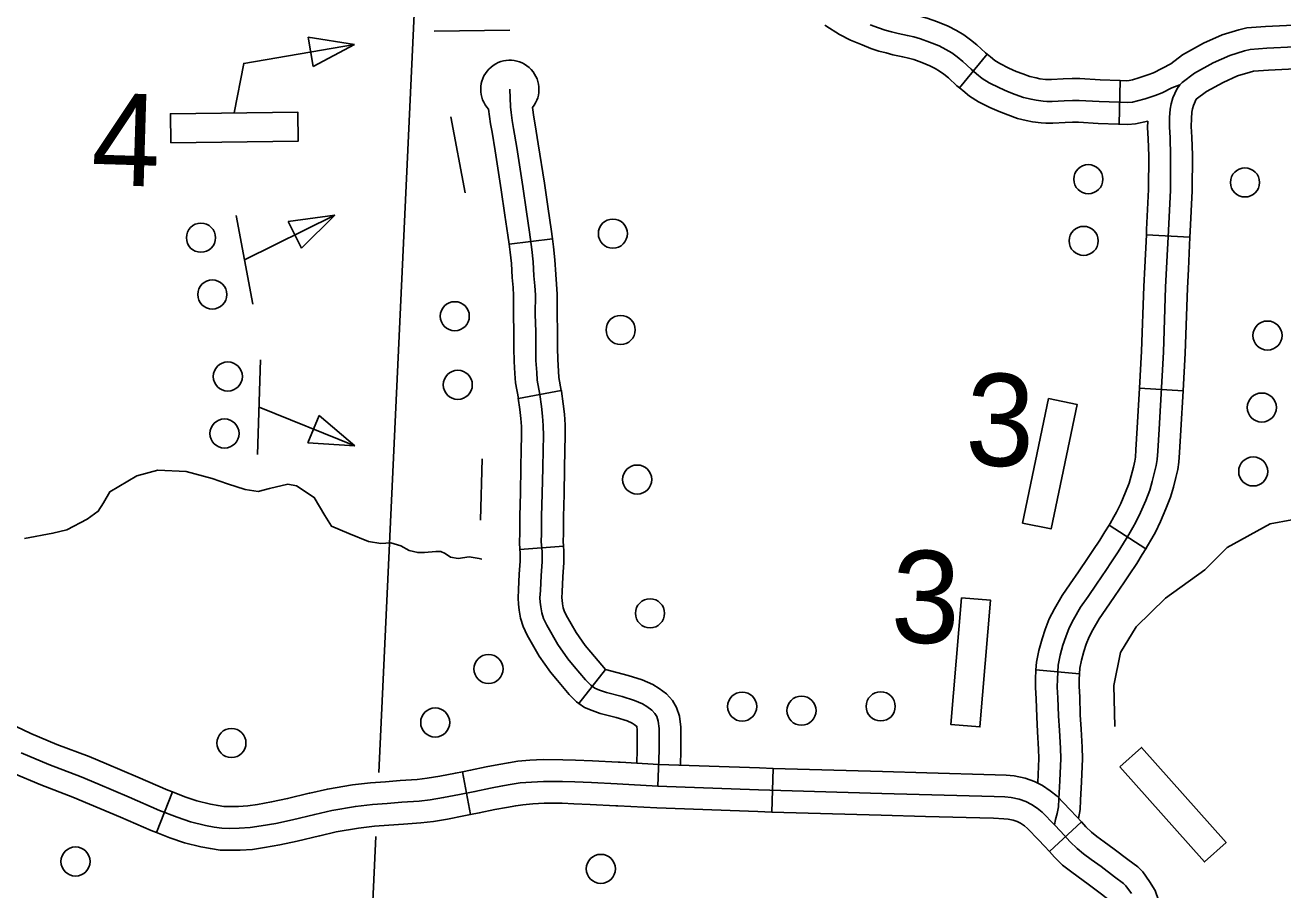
# Model space of a CAD drawing. Extents: x 653372 to 905732, y 627442 to 787275.
# Drawn here: x 709737 to 714058, y 758143 to 761114 of the extents above; entities that cross this region are included whole.
import ezdxf

# ---------------------------------------------------------------- set-up
doc = ezdxf.new("R2010")
doc.units = 0
for name, color, linetype in [('31', 7, 'Continuous'), ('32', 7, 'Continuous'), ('35', 7, 'Continuous'), ('5', 7, 'Continuous'), ('56', 7, 'Continuous')]:
    doc.layers.add(name, color=color, linetype=linetype)

msp = doc.modelspace()

# ---------------------------------------------------------------- linework, layer by layer
at = {"layer": '31'}
for p, q in [((711266.8, 758401), (711239.4, 758548.5)), ((711239.4, 758548.5), (711239.4, 758548.5)), ((712307.2, 758560), (712302.7, 758410)), ((710243, 758479), (710188.8, 758339.2)), ((713255.9, 758274.1), (713366.1, 758375.9))]:
    msp.add_line(p, q, dxfattribs=at)
for points in [[(709238.7, 758833), (709264.6, 758827.5), (709357.5, 758806.8), (709445.2, 758785.6), (709488.3, 758774.9), (709560.8, 758756.9), (709619.7, 758738.5), (709668.7, 758718.9), (709708.8, 758703.1), (709754.5, 758681.5), (709757.4, 758680.3)], [(709757.4, 758680.3), (709846.6, 758642.6), (709957.7, 758600.6), (710016.4, 758575.5), (710124.4, 758530.3), (710227.3, 758485.1), (710243, 758479)], [(710198.6, 758415.8), (710094.8, 758461.4), (709987.2, 758506.4), (709929.6, 758531), (709818.8, 758573), (709723.9, 758613.1)], [(711239.4, 758548.5), (711267.8, 758553.7), (711321.5, 758565.4), (711364.1, 758573.3), (711397.8, 758579.5), (711429.4, 758584.3), (711471.6, 758587.9), (711516.7, 758590), (711584.8, 758589.9), (711628.1, 758588.6), (711685.9, 758586.2), (711775, 758581.6), (711781.7, 758581.3)], [(711781.7, 758581.3), (711914.2, 758573.7), (712259.6, 758561.4), (712307.2, 758560)], [(710188.8, 758339.2), (710170, 758346.4), (710065.3, 758392.4), (709958, 758437.3), (709901.6, 758461.4), (709790.9, 758503.3), (709699, 758542.1)], [(711239.4, 758548.5), (711215.6, 758544), (711161.5, 758533.1), (711118.7, 758526.1), (711083.5, 758522), (711025.7, 758518.2), (710975.7, 758514), (710924, 758510.3), (710861.7, 758503.4), (710776, 758488.7), (710714.8, 758474.7), (710713.3, 758474.3)], [(712834.7, 758544.6), (712682.3, 758548.7), (712307.2, 758560)], [(713366.1, 758375.9), (713348.6, 758394.8), (713327.5, 758417.5), (713282.3, 758464.5), (713258.6, 758483.4), (713232.7, 758500.7), (713205, 758515.2), (713172.6, 758526.5), (713134.6, 758534.9), (713107.4, 758536.6), (713069.4, 758538.3), (712834.7, 758544.6)], [(713537.5, 758129.9), (713518.9, 758156), (713510.7, 758164.3), (713479.7, 758187.4), (713433.9, 758222.3), (713399.1, 758247.4), (713373.7, 758266.6), (713350.8, 758284.4), (713327.4, 758307.3), (713293.7, 758343.8), (713273, 758365.9), (713231.6, 758409), (713214.3, 758422.8), (713194.4, 758436.1), (713175.1, 758446.2), (713152, 758454.3), (713124.2, 758460.4), (713103.3, 758461.7), (713066.6, 758463.4), (712680.2, 758473.7), (712257.2, 758486.4), (711910.7, 758498.8), (711771, 758506.7), (711682.4, 758511.3), (711625.4, 758513.6), (711583.7, 758514.9), (711518.4, 758515), (711476.5, 758513), (711438.2, 758509.8), (711410.2, 758505.5), (711377.7, 758499.5), (711336.3, 758491.9), (711282.7, 758480.2), (711229.8, 758470.4), (711175, 758459.4), (711129.1, 758451.9), (711090.4, 758447.3), (711031.3, 758443.4), (710981.5, 758439.2), (710930.7, 758435.6), (710872.2, 758429.1), (710790.7, 758415.1), (710732, 758401.7), (710655.4, 758383.1), (710598, 758370.8), (710547.7, 758362.2), (710510.5, 758356.3), (710473, 758354.3), (710438.8, 758353.4), (710413.5, 758354.2), (710387, 758358.2), (710357.4, 758364.1), (710305.9, 758376.7), (710260.1, 758392), (710198.6, 758415.8)], [(710713.3, 758474.3), (710638.8, 758456.2), (710583.9, 758444.5), (710535.6, 758436.2), (710502.6, 758431), (710470, 758429.3), (710439, 758428.5), (710420.2, 758429), (710399.9, 758432), (710373.7, 758437.3), (710326.7, 758448.8), (710285.5, 758462.5), (710243, 758479)], [(711773.2, 758431.5), (711766.9, 758431.8), (711678.9, 758436.4), (711622.8, 758438.7), (711582.5, 758439.9), (711520.1, 758440), (711481.4, 758438.2), (711447, 758435.2), (711422.6, 758431.6), (711391.3, 758425.8), (711351.1, 758418.4), (711297.5, 758406.7), (711266.8, 758401)], [(711266.8, 758401), (711244, 758396.7), (711188.4, 758385.6), (711139.6, 758377.6), (711097.2, 758372.6), (711037, 758368.6), (710987.3, 758364.4), (710937.5, 758360.9), (710882.7, 758354.9), (710805.5, 758341.6), (710749.2, 758328.7), (710748.8, 758328.6)], [(712302.7, 758410), (712254.7, 758411.5), (711907.3, 758423.9), (711773.2, 758431.5)], [(712830.7, 758394.7), (712678.1, 758398.8), (712302.7, 758410)], [(713255.9, 758274.1), (713238.7, 758292.7), (713218.6, 758314.4), (713181, 758353.5), (713170, 758362.2), (713156.2, 758371.5), (713145.2, 758377.2), (713131.5, 758382), (713113.8, 758385.9), (713099.3, 758386.8), (713063.9, 758388.4), (712830.7, 758394.7)], [(713366.1, 758375.9), (713381.2, 758359.5), (713400.2, 758341), (713419.3, 758326.1), (713443.7, 758307.8), (713478.6, 758282.6), (713524.9, 758247.2), (713559.9, 758221.1), (713576.4, 758204.6), (713599.9, 758171.5), (713619.1, 758140.8), (713630.6, 758106.8), (713636.4, 758082.3), (713639.8, 758051.1), (713640.2, 758014.5), (713637.7, 757953.4), (713634.9, 757904.1)], [(710748.8, 758328.6), (710672.1, 758309.9), (710612.2, 758297.2), (710559.9, 758288.2), (710518.4, 758281.7), (710476, 758279.4), (710438.6, 758278.4), (710406.8, 758279.4), (710374, 758284.3), (710341.1, 758290.9), (710285.1, 758304.5), (710234.6, 758321.4), (710188.8, 758339.2)], [(713485.1, 757912.4), (713487.8, 757960.6), (713490.1, 758016.7), (713489.8, 758042.2), (713488.3, 758056.8), (713486.2, 758065.4), (713482.6, 758076.3), (713475.1, 758088.2), (713461.4, 758107.4), (713434.5, 758127.5), (713389.1, 758162.1), (713354.6, 758187.1), (713328.1, 758207), (713301.4, 758227.8), (713273.6, 758255), (713255.9, 758274.1)]]:
    msp.add_lwpolyline(points, dxfattribs=at)
at = {"layer": '32'}
for p, q in [((712947.1, 760898.2), (713042.3, 761014.2)), ((713495.1, 760773.8), (713499.6, 760923.7)), ((711399.9, 760361.3), (711548.7, 760380.2)), ((713738.9, 760385.5), (713589.1, 760393)), ((713715.3, 759857.7), (713565.5, 759866)), ((711431.9, 759830.5), (711579.2, 759858.7)), ((713587.1, 759314.6), (713460.9, 759395.6)), ((711437.2, 759311.6), (711586.7, 759323.3)), ((711638.9, 758782.9), (711730.9, 758899.6)), ((713359.2, 758885.3), (713209.8, 758898.4))]:
    msp.add_line(p, q, dxfattribs=at)
for points in [[(712562.1, 761242.2), (712567.6, 761238.9), (712609.2, 761212.3), (712635.9, 761198.6), (712668.7, 761185.2), (712694.5, 761174.8), (712713.2, 761168.6), (712731.8, 761163.8), (712753.8, 761158.4), (712784.4, 761151.2), (712807.9, 761146.4), (712836.3, 761138.2), (712871.2, 761125.6), (712908, 761110.8), (712936.8, 761096), (712962.6, 761080.7), (712984.9, 761063.9), (713007.1, 761046.2), (713036.6, 761018.8), (713042.3, 761014.2)], [(712484.2, 761114), (712488.2, 761111.6), (712534.4, 761082), (712573.2, 761062.1), (712612.6, 761046.1), (712642.8, 761034), (712670.6, 761024.6), (712695.2, 761018.3), (712718.7, 761012.5), (712752.1, 761004.7), (712771.9, 761000.6), (712790, 760995.4), (712817.8, 760985.4), (712845.6, 760974.2), (712864.1, 760964.7), (712879, 760955.8), (712893, 760945.3), (712909.2, 760932.4), (712938, 760905.7), (712947.1, 760898.2)], [(712640.6, 761115.6), (712668.7, 761104.4), (712691.9, 761096.6), (712713.5, 761091.1), (712736.3, 761085.5), (712768.2, 761078), (712789.9, 761073.5), (712813.2, 761066.8), (712844.5, 761055.5), (712876.8, 761042.5), (712900.4, 761030.3), (712920.8, 761018.3), (712938.9, 761004.6), (712958.1, 760989.3), (712987.3, 760962.3), (713005.9, 760947), (713025.1, 760931.1), (713049.2, 760916.2), (713084.1, 760898.8), (713112.3, 760885.9), (713138.7, 760875.9), (713167.3, 760865.7), (713193.3, 760859.5), (713210.7, 760855.7), (713235.1, 760852.8), (713247.1, 760851.9), (713265.7, 760851.9), (713307, 760854.4), (713334.9, 760855.2), (713357.8, 760855.1), (713426.9, 760851.4), (713495.6, 760848.8), (713523.4, 760847.9), (713540.9, 760849.6), (713559, 760853.4), (713584.9, 760860.8), (713619.6, 760872.3), (713643.8, 760881.4), (713676.5, 760898.5), (713703.6, 760909.4)], [(714160, 761116.2), (714148.1, 761115.3), (714094.6, 761113.8), (713998.6, 761109.3), (713934.3, 761104.2), (713906.3, 761097.7), (713849.9, 761080.4), (713785.7, 761051.8), (713713.3, 761011.9), (713672.7, 760981)], [(714097.5, 761038.9), (714003.3, 761034.4), (713945.8, 761029.9), (713925.8, 761025.2), (713876.2, 761010), (713819.1, 760984.6), (713754.3, 760948.9), (713712.4, 760917), (713703.6, 760909.4)], [(713042.3, 761014.2), (713053.6, 761004.8), (713068.9, 760992.2), (713085.7, 760981.8), (713116.4, 760966.5), (713141.3, 760955.2), (713164.6, 760946.3), (713188.7, 760937.7), (713210.1, 760932.6), (713223.2, 760929.7), (713242.4, 760927.4), (713250, 760926.9), (713263.3, 760926.9), (713303.6, 760929.4), (713334, 760930.2), (713360, 760930.1), (713430.4, 760926.3), (713498.1, 760923.7), (713499.6, 760923.7)], [(713499.6, 760923.7), (713521, 760923), (713529.6, 760923.9), (713540.9, 760926.3), (713562.7, 760932.5), (713594.6, 760943.1), (713613.2, 760950.1), (713672.7, 760981)], [(714170.7, 760966.5), (714155.5, 760965.5), (714100.3, 760963.9), (714008.1, 760959.5), (713957.2, 760955.5), (713945.3, 760952.8), (713902.6, 760939.6), (713852.5, 760917.3), (713795.3, 760885.9), (713760.5, 760859.3)], [(712947.1, 760898.2), (712958.2, 760889.1), (712981.2, 760870), (713012.6, 760850.6), (713051.8, 760831.1), (713083.4, 760816.7), (713112.9, 760805.5), (713146, 760793.7), (713176.6, 760786.4), (713198.2, 760781.7), (713227.9, 760778.1), (713244.3, 760776.9), (713268, 760776.9), (713310.4, 760779.5), (713335.7, 760780.2), (713355.5, 760780.1), (713423.5, 760776.5), (713493, 760773.8), (713495.1, 760773.8)], [(713273, 758365.9), (713277.3, 758384.1), (713282.4, 758404.6), (713286.9, 758428.1), (713288.5, 758455), (713291.8, 758517.1), (713294.9, 758593.5), (713293.7, 758629), (713290.3, 758690.2), (713287.3, 758740.2), (713285, 758802.6), (713283.1, 758839.3), (713283.3, 758866.3), (713284.4, 758891), (713286.5, 758915), (713292.8, 758948.5), (713302.5, 758983.6), (713311.9, 759011.8), (713324.1, 759043.3), (713339.2, 759072), (713363, 759114.4), (713388.8, 759150.8), (713418.2, 759193), (713451.8, 759243.3), (713467.5, 759266.6), (713492.6, 759303.7), (713510.4, 759333.9), (713529.2, 759363.3), (713542.7, 759387.3), (713553.4, 759406.1), (713569.1, 759439.5), (713587.2, 759480.6), (713601, 759516.1), (713609.4, 759545.5), (713617.5, 759577.5), (713623.1, 759601.1), (713626.3, 759621.3), (713628.3, 759649.7), (713632.8, 759726), (713647.5, 759989.9), (713655.3, 760213.1), (713658.4, 760279), (713664.9, 760408.2), (713671.7, 760546.7), (713672.3, 760665.7), (713670.4, 760726.5), (713668.5, 760764.4), (713668.7, 760796.2), (713671.3, 760824.8), (713674.4, 760843.1), (713680.5, 760863.7), (713693.9, 760894.1), (713703.6, 760909.4)], [(711402.4, 760893.5), (711404.3, 760833.1), (711406.7, 760813.9), (711410.3, 760786.5), (711415.3, 760758.4), (711425.9, 760693.9), (711446.9, 760559.2), (711459.8, 760471.9), (711470.2, 760403), (711477.8, 760342.9), (711482.5, 760300.8), (711485.4, 760252.1), (711488.1, 760218.1), (711490.1, 760187.1), (711489.6, 760120.8), (711491.4, 760059.6), (711491.2, 760004.3), (711492.2, 759961.5), (711494.6, 759920.9), (711496, 759894.3), (711505.6, 759844.5), (711511, 759803.1), (711515.1, 759769.8), (711517.1, 759738.1), (711517.5, 759702.7), (711516.8, 759654.8), (711515.7, 759592.2), (711513.8, 759504.6), (711511.4, 759425.8), (711511.2, 759367.6), (711510.3, 759338.7), (711513, 759304.7), (711513.4, 759269.4), (711509.8, 759223), (711507.5, 759170.8), (711506, 759145.8), (711507, 759131), (711508.7, 759114.7), (711512.5, 759094), (711518.6, 759074.6), (711529, 759052.2), (711566.8, 758986.2), (711601.4, 758936.6), (711623.3, 758910.5), (711662.4, 758864.4), (711680.3, 758845.5), (711694.7, 758835.4), (711710.7, 758829.1), (711734.8, 758821), (711788.1, 758806.8), (711831.2, 758793.8), (711858.1, 758781.9), (711872.5, 758772.6), (711889.8, 758759.6), (711900.5, 758748.2), (711906.9, 758737.7), (711912.3, 758722.1), (711915.2, 758696.9), (711915.2, 758622.5), (711910.7, 758498.8)], [(713738.9, 760385.5), (713739.8, 760404.5), (713746.7, 760544.6), (713747.3, 760666.7), (713745.3, 760729.5), (713743.5, 760766), (713743.7, 760792.7), (713745.7, 760815.1), (713747.6, 760826), (713751.1, 760837.9), (713760.5, 760859.3)], [(711329.6, 760825), (711336.1, 760775), (711341.4, 760745.7), (711351.9, 760682.1), (711372.8, 760548), (711385.6, 760460.8), (711395.9, 760392.6), (711399.9, 760361.3)], [(711480.1, 760830.5), (711484.4, 760798), (711489.2, 760771.1), (711500, 760705.8), (711521.1, 760570.4), (711533.9, 760482.9), (711544.5, 760413.4), (711548.7, 760380.2)], [(713495.1, 760773.8), (713525.8, 760772.8), (713552.2, 760775.3), (713593.6, 760784.1)], [(713589.1, 760393), (713590, 760411.9), (713596.7, 760548.7), (713597.3, 760664.7), (713595.4, 760723.5), (713593.5, 760762.8), (713593.6, 760784.1)], [(711548.7, 760380.2), (711552.3, 760351.8), (711557.2, 760307.2), (711560.2, 760257.3), (711562.9, 760223.5), (711565.1, 760189.2), (711564.6, 760121.6), (711566.4, 760060.6), (711566.2, 760005), (711567.1, 759964.6), (711569.5, 759925.2), (711570.7, 759903.4), (711579.2, 759858.7)], [(713565.5, 759866), (713572.6, 759993.3), (713580.4, 760216.2), (713583.5, 760282.7), (713589.1, 760393)], [(713715.3, 759857.7), (713722.4, 759986.5), (713730.3, 760210.1), (713733.3, 760275.4), (713738.9, 760385.5)], [(711399.9, 760361.3), (711403.4, 760334.1), (711407.7, 760294.4), (711410.6, 760246.9), (711413.3, 760212.7), (711415.1, 760184.9), (711414.6, 760119.9), (711416.4, 760058.5), (711416.2, 760003.6), (711417.2, 759958.4), (711419.8, 759916.7), (711421.4, 759885.2), (711431.9, 759830.5)], [(711579.1, 759859.2), (711579.6, 759856.7), (711585.4, 759812.6), (711589.9, 759776.8), (711592.1, 759740.9), (711592.6, 759702.6), (711591.8, 759653.6), (711590.7, 759590.7), (711588.8, 759502.6), (711586.4, 759424.5), (711586.2, 759366.3), (711585.4, 759340.5), (711586.7, 759323.3)], [(713460.9, 759395.6), (713464.9, 759401.9), (713477.4, 759424.1), (713486.8, 759440.6), (713500.9, 759470.6), (713517.9, 759509.3), (713529.9, 759540), (713537, 759565), (713544.6, 759595.3), (713549.5, 759615.7), (713551.7, 759629.8), (713553.4, 759654.5), (713557.9, 759730.3), (713565.5, 759866)], [(711431.6, 759832.4), (711436.6, 759793.6), (711440.4, 759762.8), (711442.2, 759735.3), (711442.5, 759702.8), (711441.9, 759656), (711440.7, 759593.7), (711438.8, 759506.5), (711436.4, 759427.1), (711436.2, 759368.9), (711435.2, 759336.9), (711437.2, 759311.5)], [(713587.1, 759314.6), (713593.5, 759324.7), (713608, 759350.4), (713620, 759371.5), (713637.4, 759408.4), (713656.5, 759451.9), (713672.2, 759492.2), (713681.9, 759526), (713690.4, 759559.7), (713696.7, 759586.5), (713700.9, 759612.7), (713703.1, 759644.9), (713707.7, 759721.7), (713715.3, 759857.7)], [(713209.8, 758898.4), (713212.1, 758925.1), (713219.6, 758965.4), (713230.7, 759005.5), (713241.4, 759037.2), (713255.7, 759074.3), (713273.3, 759107.8), (713299.5, 759154.6), (713327.4, 759193.9), (713356.2, 759235.3), (713389.5, 759285.1), (713405.3, 759308.5), (713429.1, 759343.7), (713446.5, 759373.2), (713460.9, 759395.6)], [(711437.2, 759311.6), (711438, 759301.4), (711438.3, 759271.8), (711434.9, 759227.6), (711432.6, 759174.7), (711430.8, 759145.4), (711432.3, 759124.4), (711434.4, 759104), (711439.6, 759076), (711448.5, 759047.6), (711462.3, 759017.8), (711503.3, 758946.1), (711541.8, 758890.9), (711566, 758862.1), (711606.5, 758814.4), (711631, 758788.3), (711638.9, 758782.8)], [(711586.7, 759323.3), (711587.9, 759308.1), (711588.4, 759266.9), (711584.6, 759218.5), (711582.4, 759166.9), (711581.1, 759146.2), (711581.7, 759137.6), (711583, 759125.5), (711585.5, 759112), (711588.7, 759101.7), (711595.7, 759086.7), (711630.2, 759026.4), (711660.9, 758982.3), (711680.6, 758959), (711730.9, 758899.6)], [(713359.2, 758885.3), (713360.9, 758904.8), (713365.9, 758931.6), (713374.2, 758961.6), (713382.5, 758986.3), (713392.5, 759012.2), (713405.1, 759036.3), (713426.4, 759074.3), (713450.1, 759107.6), (713480.1, 759150.7), (713514.1, 759201.5), (713529.7, 759224.6), (713556, 759263.6), (713574.3, 759294.6), (713587.1, 759314.6)], [(711730.9, 758899.6), (711808.6, 758879), (711857.3, 758864.2), (711893.7, 758848.2), (711915.5, 758834.2), (711940.1, 758815.6), (711960.7, 758793.7), (711975.2, 758769.6), (711985.8, 758738.9), (711990.2, 758701.3), (711990.2, 758621.1), (711988.4, 758571.1)], [(713216.5, 758511.6), (713219.8, 758593.8), (713218.7, 758625.7), (713215.4, 758685.9), (713212.4, 758736.6), (713210.1, 758799.3), (713208.1, 758837.7), (713208.3, 758868.3), (713209.6, 758896), (713209.8, 758898.4)], [(713355.5, 758387.4), (713361.5, 758418.9), (713363.3, 758450.9), (713366.7, 758513.6), (713369.9, 758593.2), (713368.6, 758632.4), (713365.1, 758694.5), (713362.2, 758743.8), (713360, 758805.8), (713358.1, 758841), (713358.3, 758864.4), (713359.3, 758886.1), (713359.2, 758885.3)], [(711638.9, 758782.9), (711659, 758768.9), (711684.9, 758758.6), (711713.2, 758749.1), (711767.6, 758734.7), (711805.1, 758723.3), (711822.5, 758715.6), (711829.6, 758711), (711838.9, 758704.1), (711840.2, 758692.6), (711840.2, 758623.8), (711838.5, 758578)]]:
    msp.add_lwpolyline(points, dxfattribs=at)
msp.add_arc((711402.4, 760893.5), 100, 320.9907, 223.2344, dxfattribs=at)
at = {"layer": '35'}
for points in [[(711305.9, 759278.6), (711296.9, 759281), (711262.8, 759286.7), (711225.3, 759281.6), (711199, 759285.5), (711180.7, 759298.5), (711165.3, 759305.2), (711148.2, 759305.7), (711109.2, 759302.2), (711085.8, 759301.4), (711056.4, 759308.5), (711027.4, 759324.9), (710993.4, 759335.3), (710959.1, 759333.2), (710917.3, 759339.1), (710849.6, 759367.6), (710789.7, 759392.8), (710767.4, 759429.3), (710730.4, 759491.1), (710669.3, 759530.6), (710639.9, 759536.2), (710577.2, 759522.2), (710537.9, 759510.9), (710493, 759518.5), (710432.9, 759537.4), (710379.6, 759556.2), (710290.6, 759579.8), (710193.7, 759585.1), (710121.5, 759565.5), (710028, 759510.7), (710006.6, 759472.4), (709988.6, 759443.3), (709950.5, 759416.4), (709880.9, 759379.6), (709833, 759367.8), (709735.2, 759349.7)], [(714882.6, 759071.4), (714741.9, 759131.5), (714645.6, 759185.6), (714523.2, 759279.3), (714423.9, 759360.6), (714331.5, 759410.3), (714245.9, 759428.6), (714179.3, 759426.7), (714089, 759413.7), (714014.2, 759400.3), (713867, 759318.6), (713790.3, 759242.6), (713654.4, 759144.9), (713553.6, 759046.2), (713500, 758957.8), (713477.1, 758844.9), (713480.7, 758703.9)]]:
    msp.add_lwpolyline(points, dxfattribs=at)
at = {"layer": '5'}
for points in [[(711075.2, 761176.6), (710952.7, 758545.9)], [(710942.4, 758325.4), (710892.9, 757262.5)]]:
    msp.add_lwpolyline(points, dxfattribs=at)
at = {"layer": '56'}
for p, q in [((710709.2, 761072.2), (710868.7, 761048)), ((710726.6, 760971.7), (710709.2, 761072.2)), ((710868.7, 761048), (710726.6, 760971.7)), ((710640.9, 760439), (710800.7, 760461.3)), ((710686.2, 760347.6), (710640.9, 760439)), ((710800.7, 760461.3), (710686.2, 760347.6)), ((710708.9, 759678.3), (710747, 759773)), ((710747, 759773), (710869.9, 759668.5)), ((710869.9, 759668.5), (710708.9, 759678.3))]:
    msp.add_line(p, q, dxfattribs=at)
for points in [[(711142.7, 761093.6), (711402.3, 761096.8)], [(710455.1, 760812.4), (710488.5, 760982.4), (710868.7, 761048)], [(711199.8, 760798.5), (711249.2, 760537.4)], [(710461.8, 760459.9), (710519.3, 760155.3)], [(710490.6, 760307.6), (710800.7, 760461.3)], [(710545.8, 759963.6), (710536.1, 759638.3)], [(710540.9, 759800.9), (710869.9, 759668.5)], [(711307.5, 759623.9), (711301.2, 759412.9)]]:
    msp.add_lwpolyline(points, dxfattribs=at)
for points in [[(710237.6, 760709.7), (710236.4, 760809.7), (710673.8, 760815.1), (710675.1, 760715.1)], [(713253.4, 759831.3), (713351.2, 759810.7), (713261.5, 759382.6), (713163.6, 759403.1)], [(712953.9, 759146.6), (713053.6, 759138.3), (713017.5, 758702.3), (712917.8, 758710.5)], [(713497.7, 758565.5), (713572.5, 758631.9), (713863, 758304.8), (713788.3, 758238.4)]]:
    msp.add_lwpolyline(points, close=True, dxfattribs=at)
for centre in [(713389.7, 760584.6), (713927.8, 760573.5), (710341.3, 760383.5), (711756.5, 760397.6), (713373.7, 760372.6), (710380.2, 760188.3), (711213.2, 760113.7), (711783, 760066.6), (714005.1, 760047.3), (710433.5, 759906.7), (711223.5, 759877.9), (713985.6, 759799.9), (710422.1, 759710.6), (711840, 759552.4), (713956.2, 759580.4), (711884, 759092.9), (711329.1, 758901.5), (712200.5, 758772.3), (712676.5, 758773), (712404.2, 758758.4), (711146.2, 758717.7), (710446, 758647.1), (709910.5, 758240), (711715.2, 758214.6)]:
    msp.add_circle(centre, 50, dxfattribs=at)

# ---------------------------------------------------------------- texts
for s, p in [('4', (709962.1, 760565.9)), ('3', (712964.5, 759602.8)), ('3', (712708.8, 758994.5))]:
    msp.add_text(s, height=316.8, rotation=358.28, dxfattribs=at).set_placement(p)

doc.saveas('drawing.dxf')
